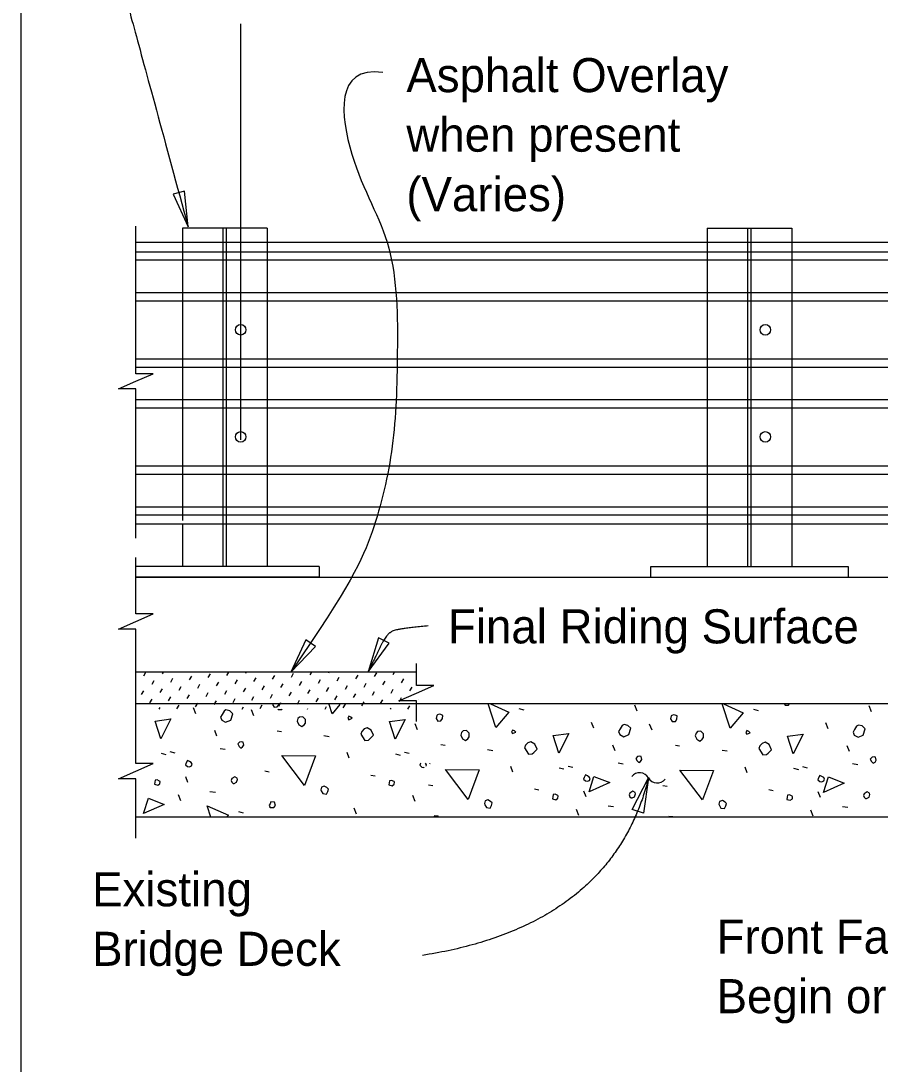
# Model space of a CAD drawing. Extents: x 21526.6 to 21598.7, y 56118.1 to 56155.9.
# Drawn here: x 21545.72 to 21550.79, y 56132.33 to 56138.5 of the extents above; entities that cross this region are included whole.
import ezdxf

# ---------------------------------------------------------------- set-up
doc = ezdxf.new("R2010")
doc.units = 0
for name, color, linetype in [('AdhocPoint_dp', 7, 'Continuous'), ('Border', 7, 'Continuous'), ('Patterning', 7, 'Continuous'), ('PlotBorder_dp', 7, 'Continuous'), ('SheetBorder_dp', 7, 'Continuous'), ('TextMisc', 7, 'Continuous')]:
    doc.layers.add(name, color=color, linetype=linetype)

msp = doc.modelspace()

# ---------------------------------------------------------------- linework, layer by layer
at = {"layer": 'AdhocPoint_dp'}
for p, q in [((21546.3955, 56135.21), (21554.1792, 56135.21)), ((21548.0534, 56134.6483), (21546.3955, 56134.6483)), ((21554.1792, 56134.46), (21546.3955, 56134.46)), ((21546.3955, 56133.7933), (21554.1792, 56133.7933))]:
    msp.add_line(p, q, dxfattribs=at)
at = {"layer": 'Patterning'}
for p, q in [((21547.0151, 56136.0224), (21547.0151, 56138.4808)), ((21546.4424, 56134.6258), (21546.4553, 56134.6482)), ((21546.553, 56134.6388), (21546.5585, 56134.6483)), ((21546.8231, 56134.6159), (21546.8361, 56134.6383)), ((21546.9337, 56134.6289), (21546.945, 56134.6483)), ((21547.0444, 56134.6418), (21547.0481, 56134.6483)), ((21547.2038, 56134.6059), (21547.2168, 56134.6283)), ((21547.3145, 56134.6189), (21547.3274, 56134.6413)), ((21547.4251, 56134.6319), (21547.4346, 56134.6483)), ((21547.5357, 56134.6448), (21547.5378, 56134.6483)), ((21547.6952, 56134.609), (21547.7082, 56134.6314)), ((21547.8058, 56134.6219), (21547.8188, 56134.6443)), ((21547.9165, 56134.6349), (21547.9242, 56134.6483)), ((21548.0271, 56134.6479), (21548.0274, 56134.6483)), ((21546.4912, 56134.577), (21546.5042, 56134.5994)), ((21546.6018, 56134.59), (21546.6148, 56134.6124)), ((21546.7125, 56134.6029), (21546.7254, 56134.6253)), ((21546.7613, 56134.5541), (21546.7743, 56134.5765)), ((21546.8719, 56134.5671), (21546.8849, 56134.5894)), ((21546.9826, 56134.58), (21546.9955, 56134.6024)), ((21547.0932, 56134.593), (21547.1062, 56134.6154)), ((21547.142, 56134.5441), (21547.155, 56134.5665)), ((21547.2527, 56134.5571), (21547.2656, 56134.5795)), ((21547.3633, 56134.5701), (21547.3763, 56134.5925)), ((21547.4739, 56134.583), (21547.4869, 56134.6054)), ((21547.5846, 56134.596), (21547.5975, 56134.6184)), ((21547.6334, 56134.5472), (21547.6464, 56134.5696)), ((21547.744, 56134.5601), (21547.757, 56134.5825)), ((21547.8547, 56134.5731), (21547.8676, 56134.5955)), ((21547.9653, 56134.5861), (21547.9783, 56134.6084)), ((21546.4294, 56134.5152), (21546.4424, 56134.5376)), ((21546.54, 56134.5282), (21546.553, 56134.5506)), ((21546.6507, 56134.5411), (21546.6636, 56134.5635)), ((21546.6995, 56134.4923), (21546.7125, 56134.5147)), ((21546.8101, 56134.5053), (21546.8231, 56134.5276)), ((21546.9208, 56134.5182), (21546.9337, 56134.5406)), ((21547.0314, 56134.5312), (21547.0444, 56134.5536)), ((21547.0802, 56134.4823), (21547.0932, 56134.5047)), ((21547.1909, 56134.4953), (21547.2038, 56134.5177)), ((21547.3015, 56134.5083), (21547.3145, 56134.5307)), ((21547.4121, 56134.5212), (21547.4251, 56134.5436)), ((21547.5228, 56134.5342), (21547.5357, 56134.5566)), ((21547.5716, 56134.4854), (21547.5846, 56134.5078)), ((21547.6822, 56134.4983), (21547.6952, 56134.5207)), ((21547.7929, 56134.5113), (21547.8058, 56134.5337)), ((21547.9035, 56134.5243), (21547.9165, 56134.5467)), ((21548.0141, 56134.5372), (21548.0271, 56134.5596)), ((21546.4782, 56134.4664), (21546.4912, 56134.4888)), ((21546.5889, 56134.4793), (21546.6018, 56134.5017)), ((21546.6377, 56134.4305), (21546.6507, 56134.4529)), ((21546.7483, 56134.4435), (21546.7613, 56134.4658)), ((21546.859, 56134.4564), (21546.8719, 56134.4788)), ((21546.9696, 56134.4694), (21546.9826, 56134.4918)), ((21547.0235, 56134.4293), (21547.0314, 56134.4429)), ((21547.1291, 56134.4335), (21547.142, 56134.4559)), ((21547.2397, 56134.4465), (21547.2527, 56134.4689)), ((21547.3503, 56134.4594), (21547.3633, 56134.4818)), ((21547.461, 56134.4724), (21547.4739, 56134.4948)), ((21547.5132, 56134.4293), (21547.5228, 56134.446)), ((21547.6204, 56134.4365), (21547.6334, 56134.4589)), ((21547.7311, 56134.4495), (21547.744, 56134.4719)), ((21547.8417, 56134.4625), (21547.8547, 56134.4849)), ((21547.9523, 56134.4754), (21547.9653, 56134.4978)), ((21548.0028, 56134.4293), (21548.0141, 56134.449)), ((21548.063, 56134.4884), (21548.0631, 56134.4886)), ((21549.3573, 56134.4169), (21549.3431, 56134.4523)), ((21550.742, 56134.4134), (21550.7278, 56134.4487)), ((21546.5339, 56134.4293), (21546.54, 56134.4399)), ((21546.7494, 56134.4017), (21546.7352, 56134.4371)), ((21546.9204, 56134.4293), (21546.9208, 56134.43)), ((21547.0935, 56134.3899), (21547.0793, 56134.4253)), ((21547.41, 56134.4293), (21547.4121, 56134.433)), ((21547.8996, 56134.4293), (21547.9035, 56134.436)), ((21548.659, 56134.4328), (21548.6873, 56134.4258)), ((21550.0437, 56134.4293), (21550.072, 56134.4222)), ((21548.0604, 56134.3079), (21548.0462, 56134.3433)), ((21549.101, 56134.3162), (21549.0868, 56134.3515)), ((21549.4451, 56134.3044), (21549.4309, 56134.3398)), ((21550.4856, 56134.3126), (21550.4715, 56134.348)), ((21546.8749, 56134.2691), (21546.8625, 56134.3027)), ((21547.2313, 56134.3016), (21547.2561, 56134.298)), ((21547.5071, 56134.2733), (21547.5372, 56134.268)), ((21546.8937, 56134.1973), (21546.9238, 56134.192)), ((21548.1983, 56134.2196), (21548.223, 56134.216)), ((21549.2265, 56134.1836), (21549.2141, 56134.2172)), ((21549.5829, 56134.216), (21549.6077, 56134.2125)), ((21550.6112, 56134.18), (21550.5988, 56134.2136)), ((21546.5449, 56134.169), (21546.5732, 56134.1619)), ((21546.5973, 56134.179), (21546.6256, 56134.1719)), ((21547.6556, 56134.1389), (21547.6432, 56134.1725)), ((21547.9296, 56134.1654), (21547.9579, 56134.1584)), ((21547.982, 56134.1754), (21548.0103, 56134.1684)), ((21548.474, 56134.1913), (21548.5041, 56134.186)), ((21549.8587, 56134.1877), (21549.8888, 56134.1824)), ((21548.6225, 56134.0569), (21548.6102, 56134.0905)), ((21548.8965, 56134.0834), (21548.9248, 56134.0764)), ((21548.9489, 56134.0934), (21548.9772, 56134.0864)), ((21549.2453, 56134.1117), (21549.2753, 56134.1064)), ((21550.0072, 56134.0534), (21549.9948, 56134.087)), ((21550.2812, 56134.0799), (21550.3095, 56134.0728)), ((21550.3336, 56134.0899), (21550.3619, 56134.0828)), ((21550.63, 56134.1082), (21550.66, 56134.1029)), ((21546.7034, 56133.9964), (21546.691, 56134.0299)), ((21547.1571, 56134.0647), (21547.1836, 56134.0594)), ((21547.7829, 56134.0399), (21547.8094, 56134.0346)), ((21548.124, 56133.9827), (21548.1505, 56133.9774)), ((21548.7498, 56133.9579), (21548.7763, 56133.9526)), ((21549.5087, 56133.9791), (21549.5352, 56133.9738)), ((21550.1345, 56133.9544), (21550.161, 56133.9491)), ((21546.661, 56133.8868), (21546.6468, 56133.9221)), ((21546.8336, 56133.9427), (21546.8654, 56133.9392)), ((21548.0457, 56133.8832), (21548.0315, 56133.9186)), ((21549.055, 56133.9108), (21549.0426, 56133.9444)), ((21550.4397, 56133.9073), (21550.4273, 56133.9409)), ((21547.0015, 56133.8243), (21547.0298, 56133.8172)), ((21547.6998, 56133.8084), (21547.6857, 56133.8437)), ((21549.0126, 56133.8012), (21548.9984, 56133.8366)), ((21549.1852, 56133.8572), (21549.217, 56133.8536)), ((21550.3973, 56133.7977), (21550.3831, 56133.833)), ((21550.5699, 56133.8536), (21550.6017, 56133.8501))]:
    msp.add_line(p, q, dxfattribs=at)
for points in [[(21547.2033, 56134.4566), (21547.2119, 56134.4412), (21547.2313, 56134.443), (21547.2402, 56134.4554), (21547.2403, 56134.4566)], [(21547.5548, 56134.4023), (21547.5372, 56134.4566)], [(21547.6008, 56134.4566), (21547.5548, 56134.4023)], [(21548.5218, 56134.3203), (21548.4763, 56134.46)], [(21548.4902, 56134.46), (21548.5995, 56134.4122), (21548.5218, 56134.3203)], [(21549.9064, 56134.3168), (21549.8599, 56134.46)], [(21549.8668, 56134.46), (21549.9842, 56134.4087), (21549.9064, 56134.3168)], [(21550.2285, 56134.46), (21550.2311, 56134.454), (21550.2275, 56134.4576)], [(21550.2311, 56134.454), (21550.2523, 56134.454), (21550.2582, 56134.46)], [(21546.9032, 56134.3646), (21546.9261, 56134.3522), (21546.9562, 56134.3646), (21546.9686, 56134.4017), (21546.9509, 56134.4194), (21546.9279, 56134.4247), (21546.9173, 56134.4176), (21546.9049, 56134.3982), (21546.8961, 56134.3823), (21546.9032, 56134.3646)], [(21547.2354, 56134.4293), (21547.2364, 56134.4269), (21547.234, 56134.4293)], [(21547.2364, 56134.4269), (21547.2576, 56134.4269), (21547.2601, 56134.4293)], [(21547.348, 56134.3581), (21547.3586, 56134.3369), (21547.3763, 56134.3263), (21547.3904, 56134.3369), (21547.3975, 56134.3475), (21547.3975, 56134.3687), (21547.3816, 56134.3846), (21547.3622, 56134.3829), (21547.3533, 56134.374), (21547.348, 56134.3581)], [(21547.6538, 56134.367), (21547.6733, 56134.3758), (21547.6662, 56134.3829), (21547.6538, 56134.3882), (21547.6485, 56134.3758), (21547.6538, 56134.367)], [(21548.17, 56134.3751), (21548.1788, 56134.3592), (21548.1983, 56134.361), (21548.2071, 56134.3734), (21548.2089, 56134.3928), (21548.1965, 56134.3981), (21548.1877, 56134.3999), (21548.177, 56134.3963), (21548.1735, 56134.3928), (21548.17, 56134.3751)], [(21549.5547, 56134.3716), (21549.5635, 56134.3557), (21549.5829, 56134.3574), (21549.5918, 56134.3698), (21549.5935, 56134.3893), (21549.5812, 56134.3946), (21549.5723, 56134.3963), (21549.5617, 56134.3928), (21549.5582, 56134.3893), (21549.5547, 56134.3716)], [(21546.5425, 56134.255), (21546.509, 56134.3593), (21546.6026, 56134.3716), (21546.5425, 56134.255)], [(21547.7245, 56134.2821), (21547.7475, 56134.245), (21547.7705, 56134.2468), (21547.7793, 56134.2556), (21547.7988, 56134.275), (21547.7864, 56134.3051), (21547.7617, 56134.3192), (21547.744, 56134.3122), (21547.7299, 56134.298), (21547.7245, 56134.2821)], [(21547.9272, 56134.2514), (21547.8936, 56134.3557), (21547.9873, 56134.3681), (21547.9272, 56134.2514)], [(21549.2548, 56134.279), (21549.2777, 56134.2667), (21549.3078, 56134.279), (21549.3202, 56134.3162), (21549.3025, 56134.3338), (21549.2795, 56134.3391), (21549.2689, 56134.3321), (21549.2565, 56134.3126), (21549.2477, 56134.2967), (21549.2548, 56134.279)], [(21550.6394, 56134.2755), (21550.6624, 56134.2631), (21550.6925, 56134.2755), (21550.7048, 56134.3126), (21550.6872, 56134.3303), (21550.6642, 56134.3356), (21550.6536, 56134.3285), (21550.6412, 56134.3091), (21550.6324, 56134.2932), (21550.6394, 56134.2755)], [(21548.3149, 56134.2761), (21548.3255, 56134.2549), (21548.3432, 56134.2443), (21548.3574, 56134.2549), (21548.3644, 56134.2655), (21548.3644, 56134.2867), (21548.3485, 56134.3026), (21548.3291, 56134.3009), (21548.3202, 56134.292), (21548.3149, 56134.2761)], [(21548.6208, 56134.285), (21548.6402, 56134.2938), (21548.6331, 56134.3009), (21548.6208, 56134.3062), (21548.6155, 56134.2938), (21548.6208, 56134.285)], [(21548.8941, 56134.1694), (21548.8605, 56134.2737), (21548.9542, 56134.2861), (21548.8941, 56134.1694)], [(21549.6996, 56134.2726), (21549.7102, 56134.2514), (21549.7279, 56134.2408), (21549.742, 56134.2514), (21549.7491, 56134.262), (21549.7491, 56134.2832), (21549.7332, 56134.2991), (21549.7138, 56134.2973), (21549.7049, 56134.2885), (21549.6996, 56134.2726)], [(21550.0054, 56134.2814), (21550.0249, 56134.2903), (21550.0178, 56134.2973), (21550.0054, 56134.3026), (21550.0001, 56134.2903), (21550.0054, 56134.2814)], [(21550.2788, 56134.1659), (21550.2452, 56134.2702), (21550.3389, 56134.2826), (21550.2788, 56134.1659)], [(21547.0051, 56134.2096), (21547.0157, 56134.199), (21547.0263, 56134.2061), (21547.0334, 56134.2167), (21547.0298, 56134.2344), (21547.021, 56134.2362), (21547.0086, 56134.2344), (21546.998, 56134.2238), (21547.0051, 56134.2096)], [(21548.6915, 56134.2001), (21548.7145, 56134.163), (21548.7374, 56134.1648), (21548.7463, 56134.1736), (21548.7657, 56134.193), (21548.7533, 56134.2231), (21548.7286, 56134.2372), (21548.7109, 56134.2302), (21548.6968, 56134.216), (21548.6915, 56134.2001)], [(21550.0761, 56134.1966), (21550.0991, 56134.1595), (21550.1221, 56134.1612), (21550.1309, 56134.1701), (21550.1504, 56134.1895), (21550.138, 56134.2196), (21550.1133, 56134.2337), (21550.0956, 56134.2266), (21550.0815, 56134.2125), (21550.0761, 56134.1966)], [(21547.3922, 56133.9781), (21547.2579, 56134.1548), (21547.4576, 56134.1531), (21547.3922, 56133.9781)], [(21549.3567, 56134.1241), (21549.3673, 56134.1135), (21549.3779, 56134.1206), (21549.3849, 56134.1312), (21549.3814, 56134.1488), (21549.3726, 56134.1506), (21549.3602, 56134.1488), (21549.3496, 56134.1382), (21549.3567, 56134.1241)], [(21550.7413, 56134.1206), (21550.7519, 56134.11), (21550.7626, 56134.117), (21550.7696, 56134.1276), (21550.7661, 56134.1453), (21550.7573, 56134.1471), (21550.7449, 56134.1453), (21550.7343, 56134.1347), (21550.7413, 56134.1206)], [(21546.6999, 56134.0906), (21546.7122, 56134.0888), (21546.7246, 56134.0941), (21546.7282, 56134.1047), (21546.7229, 56134.1136), (21546.7122, 56134.1206), (21546.6999, 56134.1259), (21546.6928, 56134.1118), (21546.6893, 56134.1012), (21546.6999, 56134.0906)], [(21548.0789, 56134.1111), (21548.0775, 56134.1082), (21548.0739, 56134.0976), (21548.0845, 56134.087)], [(21548.0845, 56134.087), (21548.0969, 56134.0853), (21548.0988, 56134.0861)], [(21548.1101, 56134.0931), (21548.1128, 56134.1012), (21548.1075, 56134.11), (21548.1059, 56134.1111)], [(21548.133, 56134.1072), (21548.1342, 56134.1111)], [(21548.3591, 56133.8961), (21548.2248, 56134.0728), (21548.4245, 56134.0711), (21548.3591, 56133.8961)], [(21546.506, 56133.9851), (21546.5255, 56133.9798), (21546.5379, 56133.9887), (21546.5396, 56134.001), (21546.5361, 56134.0046), (21546.522, 56134.0116), (21546.5096, 56134.0099), (21546.5078, 56133.9975), (21546.506, 56133.9851)], [(21546.9697, 56133.9904), (21546.9768, 56133.9904), (21546.9909, 56133.9975), (21546.9962, 56134.0134), (21546.9945, 56134.0223), (21546.9803, 56134.0293), (21546.9626, 56134.0187), (21546.9591, 56134.0081), (21546.9626, 56133.9975), (21546.9697, 56133.9904)], [(21549.0515, 56134.005), (21549.0638, 56134.0033), (21549.0762, 56134.0086), (21549.0798, 56134.0192), (21549.0744, 56134.028), (21549.0638, 56134.0351), (21549.0515, 56134.0404), (21549.0444, 56134.0262), (21549.0409, 56134.0156), (21549.0515, 56134.005)], [(21549.0738, 56133.9403), (21549.1021, 56134.0322), (21549.1958, 56133.9951), (21549.0738, 56133.9403)], [(21549.7438, 56133.8925), (21549.6095, 56134.0693), (21549.8092, 56134.0675), (21549.7438, 56133.8925)], [(21550.4361, 56134.0015), (21550.4485, 56133.9997), (21550.4609, 56134.005), (21550.4644, 56134.0156), (21550.4591, 56134.0245), (21550.4485, 56134.0316), (21550.4361, 56134.0369), (21550.4291, 56134.0227), (21550.4255, 56134.0121), (21550.4361, 56134.0015)], [(21550.4585, 56133.9367), (21550.4868, 56134.0286), (21550.5805, 56133.9915), (21550.4585, 56133.9367)], [(21547.4912, 56133.9462), (21547.5, 56133.9303), (21547.5213, 56133.9268), (21547.5301, 56133.9427), (21547.5336, 56133.9568), (21547.5248, 56133.9657), (21547.5089, 56133.9745), (21547.493, 56133.9692), (21547.4877, 56133.9533), (21547.4912, 56133.9462)], [(21547.8907, 56133.9816), (21547.9102, 56133.9763), (21547.9225, 56133.9851), (21547.9243, 56133.9975), (21547.9208, 56134.001), (21547.9066, 56134.0081), (21547.8943, 56134.0063), (21547.8925, 56133.994), (21547.8907, 56133.9816)], [(21546.4412, 56133.8116), (21546.4695, 56133.9035), (21546.5632, 56133.8664), (21546.4412, 56133.8116)], [(21548.4581, 56133.8642), (21548.467, 56133.8483), (21548.4882, 56133.8448), (21548.497, 56133.8607), (21548.5006, 56133.8748), (21548.4917, 56133.8837), (21548.4758, 56133.8925), (21548.4599, 56133.8872), (21548.4546, 56133.8713), (21548.4581, 56133.8642)], [(21548.8576, 56133.8996), (21548.8771, 56133.8943), (21548.8895, 56133.9031), (21548.8912, 56133.9155), (21548.8877, 56133.919), (21548.8735, 56133.9261), (21548.8612, 56133.9243), (21548.8594, 56133.912), (21548.8576, 56133.8996)], [(21549.3213, 56133.9049), (21549.3284, 56133.9049), (21549.3425, 56133.912), (21549.3478, 56133.9279), (21549.3461, 56133.9367), (21549.3319, 56133.9438), (21549.3142, 56133.9332), (21549.3107, 56133.9226), (21549.3142, 56133.912), (21549.3213, 56133.9049)], [(21549.8428, 56133.8607), (21549.8516, 56133.8448), (21549.8729, 56133.8413), (21549.8817, 56133.8572), (21549.8852, 56133.8713), (21549.8764, 56133.8801), (21549.8605, 56133.889), (21549.8446, 56133.8837), (21549.8393, 56133.8678), (21549.8428, 56133.8607)], [(21550.2423, 56133.8961), (21550.2618, 56133.8908), (21550.2741, 56133.8996), (21550.2759, 56133.912), (21550.2724, 56133.9155), (21550.2582, 56133.9226), (21550.2459, 56133.9208), (21550.2441, 56133.9084), (21550.2423, 56133.8961)], [(21550.706, 56133.9014), (21550.7131, 56133.9014), (21550.7272, 56133.9084), (21550.7325, 56133.9243), (21550.7307, 56133.9332), (21550.7166, 56133.9403), (21550.6989, 56133.9296), (21550.6954, 56133.919), (21550.6989, 56133.9084), (21550.706, 56133.9014)], [(21546.8388, 56133.79), (21546.8165, 56133.8585), (21546.9421, 56133.8037), (21546.9305, 56133.79)], [(21547.1889, 56133.849), (21547.2101, 56133.849), (21547.2207, 56133.8596), (21547.2154, 56133.8791), (21547.1925, 56133.8808), (21547.1889, 56133.8702), (21547.1836, 56133.8614), (21547.1889, 56133.849), (21547.1854, 56133.8525)], [(21546.5368, 56133.79), (21546.5302, 56133.7913), (21546.5262, 56133.79)], [(21548.1834, 56133.7933), (21548.1824, 56133.7971), (21548.1594, 56133.7988), (21548.1575, 56133.7933)], [(21549.5671, 56133.7933), (21549.567, 56133.7935), (21549.544, 56133.7953), (21549.5434, 56133.7933)]]:
    msp.add_lwpolyline(points, dxfattribs=at)
at = {"layer": 'PlotBorder_dp'}
msp.add_line((21545.7163, 56153.2556), (21545.7163, 56127.3172), dxfattribs=at)
for points in [[(21546.7043, 56137.2817), (21546.6837, 56137.4919), (21546.6156, 56137.4734)], [(21547.3105, 56134.6482), (21547.4577, 56134.7997), (21547.3996, 56134.8397)], [(21547.7672, 56134.6496), (21547.8919, 56134.8201), (21547.8288, 56134.8517)], [(21549.4247, 56134.0233), (21549.3942, 56133.8143), (21549.3271, 56133.836)]]:
    msp.add_lwpolyline(points, close=True, dxfattribs=at)
for points in [[(21546.3955, 56135.4395), (21546.3955, 56136.3228), (21546.2921, 56136.3228), (21546.3955, 56136.3678), (21546.4988, 56136.4128), (21546.3955, 56136.4128), (21546.3955, 56137.2857)], [(21546.3955, 56134.4321), (21546.3955, 56134.9022), (21546.2921, 56134.9022), (21546.3955, 56134.9472), (21546.4988, 56134.9922), (21546.3955, 56134.9922), (21546.3955, 56135.3267)], [(21548.0534, 56134.3575), (21548.0534, 56134.4784), (21547.9501, 56134.4784), (21548.0534, 56134.5234), (21548.1568, 56134.5684), (21548.0534, 56134.5684), (21548.0534, 56134.699)], [(21546.3955, 56133.667), (21546.3955, 56134.0177), (21546.2921, 56134.0177), (21546.3955, 56134.0627), (21546.4988, 56134.1077), (21546.3955, 56134.1077), (21546.3955, 56134.4321)]]:
    msp.add_lwpolyline(points, dxfattribs=at)
for centre, start, end in [((21549.3723, 56133.9936), 30.00813, 141.73535), ((21549.4755, 56134.0532), 210.00813, 321.73535)]:
    msp.add_arc(centre, 0.0596, start, end, dxfattribs=at)
for points, degree in [([(21546.5388, 56138.9775), (21546.3833, 56138.9775), (21546.2629, 56138.9122), (21546.318, 56138.7015), (21546.7043, 56137.2817)], 2), ([(21547.8542, 56138.1934), (21547.5677, 56138.2343), (21547.6407, 56137.6336), (21547.9384, 56137.195), (21547.9442, 56136.5212), (21547.927, 56135.9787), (21547.8072, 56135.4705), (21547.6617, 56135.1578), (21547.3105, 56134.6481)], 3), ([(21548.1235, 56134.922), (21547.9499, 56134.9066), (21547.8757, 56134.8752), (21547.8101, 56134.7353), (21547.7672, 56134.6496)], 2), ([(21549.4247, 56134.0233), (21549.2041, 56133.1495), (21548.0898, 56132.9735)], 2)]:
    msp.add_open_spline(points, degree=degree, dxfattribs=at)
at = {"layer": 'SheetBorder_dp'}
for p, q in [((21546.9109, 56135.2726), (21546.9109, 56137.2726)), ((21546.9317, 56135.2726), (21546.9317, 56137.2726)), ((21550.0101, 56135.2724), (21550.0101, 56137.2724)), ((21550.0309, 56135.2724), (21550.0309, 56137.2724)), ((21546.6713, 56137.1892), (21546.6713, 56135.5456)), ((21547.1713, 56137.1892), (21547.1713, 56135.5225)), ((21549.7705, 56137.1891), (21549.7705, 56135.5224)), ((21550.2705, 56137.1891), (21550.2705, 56135.5224))]:
    msp.add_line(p, q, dxfattribs=at)
at = {"layer": 'TextMisc'}
for p, q in [((21547.1713, 56137.2726), (21546.6713, 56137.2726)), ((21546.6713, 56137.2726), (21546.6713, 56137.1892)), ((21547.1713, 56137.2726), (21547.1713, 56137.1892)), ((21549.7705, 56137.2724), (21550.2705, 56137.2724)), ((21549.7705, 56137.2724), (21549.7705, 56137.1892)), ((21550.2705, 56137.2724), (21550.2705, 56137.1891)), ((21552.8484, 56137.1892), (21546.3955, 56137.1892)), ((21546.3955, 56137.1336), (21552.8484, 56137.1336)), ((21546.3955, 56137.0854), (21552.8484, 56137.0854)), ((21546.3955, 56136.8926), (21552.8484, 56136.8926)), ((21546.3955, 56136.8444), (21552.8484, 56136.8444)), ((21546.3955, 56136.5004), (21552.8484, 56136.5004)), ((21546.3955, 56136.4522), (21552.8484, 56136.4522)), ((21546.3955, 56136.2594), (21552.8484, 56136.2594)), ((21546.3955, 56136.2112), (21552.8484, 56136.2112)), ((21546.3955, 56135.8673), (21552.8484, 56135.8673)), ((21546.3955, 56135.8191), (21552.8484, 56135.8191)), ((21546.3955, 56135.6262), (21552.8484, 56135.6262)), ((21546.3955, 56135.578), (21552.8484, 56135.578)), ((21552.8484, 56135.5225), (21546.3955, 56135.5225)), ((21546.6713, 56135.5225), (21546.6713, 56135.2726)), ((21547.1713, 56135.5225), (21547.1713, 56135.2726)), ((21549.7705, 56135.5224), (21549.7705, 56135.2724)), ((21550.2705, 56135.5224), (21550.2705, 56135.2724)), ((21547.4788, 56135.2726), (21546.3955, 56135.2726)), ((21547.1713, 56135.2726), (21546.6713, 56135.2726)), ((21547.4788, 56135.2726), (21547.4788, 56135.2101)), ((21549.4371, 56135.2724), (21550.6038, 56135.2724)), ((21549.4371, 56135.2099), (21549.4371, 56135.2724)), ((21549.7705, 56135.2724), (21550.2705, 56135.2724)), ((21550.6038, 56135.2724), (21550.6038, 56135.2099)), ((21547.4788, 56135.2101), (21546.3955, 56135.2101)), ((21549.4371, 56135.2099), (21550.6038, 56135.2099))]:
    msp.add_line(p, q, dxfattribs=at)
for centre in [(21547.0151, 56136.6725), (21550.1142, 56136.6723), (21547.0151, 56136.0393), (21550.1142, 56136.0392)]:
    msp.add_circle(centre, 0.0312, dxfattribs=at)

# ---------------------------------------------------------------- texts
at = {"layer": 'Border'}
msp.add_text('Final Riding Surface', height=0.2016, dxfattribs=at).set_placement((21548.2396, 56134.8183))
at = {"layer": 'PlotBorder_dp'}
for s, p in [('Asphalt Overlay', (21547.9936, 56138.0774)), ('when present', (21547.9936, 56137.7254)), ('(Varies)', (21547.9936, 56137.3734)), ('Existing ', (21546.1373, 56133.2637)), ('Front Face of Backwall &', (21549.8265, 56132.9839)), ('Bridge Deck', (21546.1373, 56132.9117)), ('Begin or End Bridge', (21549.8265, 56132.6319))]:
    msp.add_text(s, height=0.2016, dxfattribs=at).set_placement(p)

doc.saveas('drawing.dxf')
